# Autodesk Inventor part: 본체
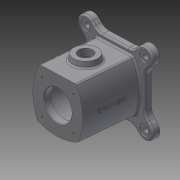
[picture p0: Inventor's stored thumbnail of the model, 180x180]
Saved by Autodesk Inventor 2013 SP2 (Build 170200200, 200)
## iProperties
Created: 2022-01
Part Number: 본체
Material: Generic
Document SubType Name: Modeling
Designer: i
Density: 1 g/cm^3
Author: i
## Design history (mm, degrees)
sketch "스케치1"
  geometry: L1 (-45, -45)-(45, -45); L2 (45, -45)-(45, 45); L3 (45, 45)-(-45, 45); L4 (-45, 45)-(-45, -45); L5 (-45, -45)-(45, 45); L6 (45, -45)-(-45, 45); 1 further point
  constraints: 12 end point, 2 midpoint, 2 parallel, 1 horizontal, 1 perpendicular
  dimensions: "d0" = 90 distance of L3.end L2.end; "d1" = 90 distance of L2.end L1.end
extrude "돌출1" new body sketch "스케치1" distance "d3" = 98; taper "d4" = 0 deg
sketch "스케치2"
  geometry: L1 (-45, -45)-(45, -45) reference; L2 (45, -45)-(45, 45) reference; L3 (-45, 45)-(-45, -45) reference; L4 (-45, -45)-(-45, 45) reference; L5 (-45, 45)-(45, 45) reference; L6 (45, 45)-(45, -45) reference; L7 (45, -45)-(-45, -45) reference; A1 r 90 centre (45, 0) between (-32.942, 45) and (-32.942, -45); A2 r 90 centre (-45, 0) between (32.942, -45) and (32.942, 45); A3 r 90 centre (0, 45) between (-45, -32.942) and (45, -32.942); 4 further points
  constraints: 9 point on circle, 6 point on line, 3 centre point, 3 midpoint
  dimensions: "d5" = 90 radius of A1; "d6" = 90 radius of A2; "d7" = 90 radius of A3
extrude "돌출2" cut sketch "스케치2" stored distance "d8" = 10; taper "d9" = 0 deg
sketch "스케치3"
  geometry: L1 (0, 98)-(0, 0); L2 (-45, 0)-(-45, 98) reference; L3 (-45, 98)-(45, 98) reference; L4 (45, 98)-(45, 0) reference; L5 (45, 0)-(-45, 0) reference; L6 (25, 98)-(25, 86); L7 (25, 86)-(37, 86); L8 (37, 86)-(37, 0); L9 (37, 0)-(0, 0); L10 (25, 98)-(0, 98)
  constraints: 12 end point, 4 perpendicular, 2 point on line, 1 parallel, 1 vertical
  dimensions: "d13" = 50 diameter of L6 L1; "d15" = 12 distance of L6.start L6.end; "d16" = 74 diameter of L8 L1
revolve "회전1" sketch "스케치3" stored, may be unused: angle "d17" = 90 deg
node "작업 평면1"
sketch "스케치4"
  geometry: L1 (-53, -53)-(53, -53); L2 (53, -53)-(53, 53); L3 (53, 53)-(-53, 53); L4 (-53, 53)-(-53, -53); L5 (-53, -53)-(53, 53); L6 (53, -53)-(-53, 53); 1 further point
  constraints: 12 end point, 2 midpoint, 2 parallel, 1 horizontal, 1 perpendicular
  dimensions: "d19" = 106 distance of L3.end L2.end; "d20" = 106 distance of L2.end L1.end
extrude "돌출3" join sketch "스케치4" distance "d21" = 12; taper "d22" = 0 deg
sketch "스케치5"
  geometry: C1 r 25 at (0, 0); 1 further point
  constraints: 1 centre point, 1 coincident
  dimensions: "d23" = 50 diameter of C1
extrude "돌출4" cut sketch "스케치5" distance "d24" = 12; taper "d25" = 0 deg
fillet "모깎기1" dims "d26" = 3
fillet "모깎기2" dims "d27" = 3
sketch "스케치6"
  geometry: L1 (-53, 53)-(53, 53) reference; L2 (53, 53)-(53, -53) reference; L3 (53, -53)-(-53, -53) reference; L4 (-53, -53)-(-53, 53) reference; L5 (-53, 53)-(53, 53) reference; L6 (-53, 31.787)-(-63.607, 42.393); L7 (-31.787, 53)-(-42.393, 63.607); C1 r 25 at (0, 0) reference; A1 r 15 centre (-53, 53) between (-63.607, 42.393) and (-42.393, 63.607)
  constraints: 4 end point, 2 point on circle, 2 point on line, 2 tangent, 1 centre point, 1 coincident, 1 parallel
  dimensions: "d32" = 30 diameter of A1; "d33" = 45 deg angle of L7 L1
extrude "돌출5" join sketch "스케치6" distance "d34" = 12; taper "d35" = 0 deg
sketch "스케치8"
  geometry: C1 r 9 at (53, 53); A1 r 15 centre (53, 53) between (63.607, 42.393) and (42.393, 63.607) reference; 1 further point
  constraints: 1 centre point, 1 coincident
  dimensions: "d36" = 18 diameter of C1
extrude "돌출6" cut sketch "스케치8" distance "d37" = 2; taper "d38" = 0 deg
sketch "스케치9"
  geometry: C1 r 9 at (0, 0) reference; C2 r 4.5 at (0, 0); 1 further point
  constraints: 1 centre point, 1 coincident
  dimensions: "d39" = 9 diameter of C2
extrude "돌출7" cut sketch "스케치9" stored distance "d40" = 2; taper "d41" = 0 deg
node "작업 평면2"
sketch "스케치10"
  geometry: L1 (-31.787, -12)-(31.787, -12) reference; L2 (0, -12)-(0, 49); C1 r 20 at (1.415, 49); 1 further point
  constraints: 2 end point, 1 centre point, 1 midpoint, 1 perpendicular
  dimensions: "d46" = 61 distance of L2.start L2.end; "d47" = 40 diameter of C1
extrude "돌출8" join sketch "스케치10" stored distance "d48" = 2; taper "d49" = 10 deg
sketch "스케치11"
  geometry: C1 r 20 at (0, 0) reference; C2 r 12 at (0, 0); 1 further point
  constraints: 1 centre point, 1 coincident
  dimensions: "d50" = 24 diameter of C2
extrude "돌출9" cut sketch "스케치11" distance "d51" = 13; taper "d52" = 0 deg
sketch "스케치12"
  geometry: L1 (-53, -12)-(-53, 0) reference; L2 (-53, 0)-(-45, 0) reference; L3 (-45, 0)-(-45, 98) reference; L4 (-45, 98)-(-25, 98) reference; L5 (-25, 98)-(-25, 86) reference; L6 (-25, 86)-(-34, 86) reference; L7 (-37, 83)-(-37, 3) reference; L8 (-34, 0)-(-25, 0) reference; L9 (-25, 0)-(-25, -12) reference; L10 (-25, -12)-(-53, -12) reference; L11 (45, 0)-(53, 0) reference; L12 (53, 0)-(53, -12) reference; L13 (53, -12)-(25, -12) reference; L14 (25, -12)-(25, 0) reference; L15 (25, 0)-(34, 0) reference; L16 (37, 3)-(37, 83) reference; L17 (34, 86)-(25, 86) reference; L18 (25, 86)-(25, 98) reference; L19 (25, 98)-(45, 98) reference; L20 (45, 98)-(45, 0) reference; L21 (25, -12)-(-25, -12) reference; L22 (0, -12)-(0, 49); C1 r 15 at (0, 49); A1 r 3 centre (-34, 83) between (-34, 86) and (-37, 83) reference; A2 r 3 centre (-34, 3) between (-37, 3) and (-34, 0) reference; A3 r 3 centre (34, 3) between (34, 0) and (37, 3) reference; A4 r 3 centre (34, 83) between (37, 83) and (34, 86) reference; 1 further point
  constraints: 2 end point, 1 centre point, 1 coincident, 1 midpoint, 1 perpendicular
  dimensions: "d54" = 61 distance of L22.start L22.end; "d55" = 30 diameter of C1
extrude "돌출10" cut sketch "스케치12" distance "d56" = 42; taper "d57" = 0 deg
chamfer "모따기3" distance "d97" = 1; stored, may be unused: second distance "d98" = 2, angle "d99" = 45 deg
chamfer "모따기2" distance "d61" = 1; stored, may be unused: second distance "d62" = 2, angle "d63" = 45 deg
sketch "스케치13"
  geometry: L1 (0, 0)-(28.284, 28.284); L2 (-31.787, -53)-(31.787, -53) reference; C1 r 26 at (0, 0) reference; 1 further point
  constraints: 2 end point, 1 coincident
  dimensions: "d64" = 40 distance of L1.start L1.end; "d65" = 45 deg angle of L2 L1
hole "구멍1" sketch "스케치13" at (28.284, 28.284) diameter "d66" = 3.242; stored, may be unused: countersink angle "d70" = 90 deg, drill point angle "d72" = 118 deg; dims "d67" = 9, "d68" = 4, "d69" = 2, "d71" = 11
sketch "스케치15"
  geometry: L1 (-42.393, -63.607)-(-31.787, -53) reference; L2 (0, 0)-(28.284, 28.284); C1 r 26 at (0, 0) reference; 1 further point
  constraints: 2 end point, 1 coincident, 1 parallel
  dimensions: "d76" = 40 distance of L2.start L2.end
hole "구멍2" sketch "스케치15" at (28.284, 28.284) diameter "d77" = 3.242; stored, may be unused: countersink angle "d81" = 90 deg, drill point angle "d83" = 118 deg; dims "d78" = 9, "d79" = 4, "d80" = 2, "d82" = 11
fillet "모깎기3" dims "d87" = 20
fillet "모깎기4" dims "d88" = 3
fillet "모깎기5" dims "d89" = 3
fillet "모깎기6" dims "d90" = 3
fillet "모깎기7" dims "d91" = 3
node "작업 평면4"
sketch "스케치16"
  geometry: L1 (-23.503, -12)-(23.503, -12) reference; L2 (55, 69)-(55, 29) reference; 2 further points
  constraints: 1 other
feature "엠보싱1" sketch "스케치16" dims "d0" = 90, "d1" = 90, "d7" = 90, "d95" = 0.5, "d96" = 0
node "솔리드1"
pattern_circular "원형 패턴1" dims "d43" = 360 deg
pattern_circular "원형 패턴2" dims angle "d74" = 360 deg
pattern_circular "원형 패턴3" dims angle "d85" = 360 deg
node "절단 모서리 투영1"
node "절단 모서리 투영2"
node "절단 모서리 투영3"
node "절단 모서리 투영4"
other parameters: "d18" = -12, "d45" = 55
